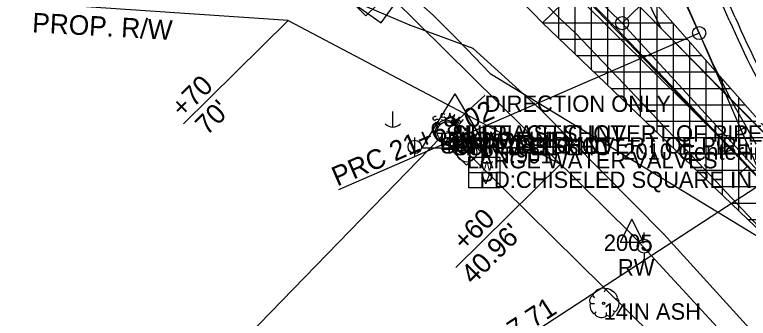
# Model space of a CAD drawing. Extents: x 1660112 to 1662239, y 668919 to 671377.
# Drawn here: x 1661159 to 1661383, y 670095.9 to 670188.6 of the extents above; entities that cross this region are included whole.
import ezdxf

# ---------------------------------------------------------------- set-up
doc = ezdxf.new("R2010")
doc.units = 0
for name, color, linetype in [('R_Annotation', 7, 'Continuous'), ('R_Axis', 7, 'Continuous'), ('R_Horz Alg', 7, 'Continuous'), ('R_Horz Alg Annot', 7, 'Continuous'), ('R_Proposed Const Limits_Cut', 7, 'Continuous'), ('R_Proposed Const Limits_Fill', 7, 'Continuous'), ('R_Proposed Road_Lane', 7, 'Continuous'), ('R_Proposed Road_Shoulder', 7, 'Continuous'), ('R_ROW', 7, 'Continuous'), ('R_ROW Annot', 7, 'Continuous'), ('R_Water Annot', 7, 'Continuous'), ('S_EDGE_CONCRETE', 7, 'Continuous'), ('S_EDGE_PAVEMENT', 7, 'Continuous'), ('S_EXIST_ROW', 7, 'Continuous'), ('S_EXIST_ROW_ANNOT', 7, 'Continuous'), ('S_EXISTING_ALIGNMENT', 7, 'Continuous'), ('S_EXISTING_ALIGNMENT_ANNOT', 7, 'Continuous'), ('S_GRD_PT_SYM', 7, 'Continuous'), ('S_MANHOLE_ANNOT', 7, 'Continuous'), ('S_MISC_TOPO_POINT', 7, 'Continuous'), ('S_PAVEMENT_CROWN', 7, 'Continuous'), ('S_PRIMARY_CTL', 7, 'Continuous'), ('S_PRIMARY_CTL_ANNOT', 7, 'Continuous'), ('S_SANITARY_SEWER', 7, 'Continuous'), ('S_SANITARY_SEWER_ANNOT', 7, 'Continuous'), ('S_TREE', 7, 'Continuous'), ('S_TREE_ANNOT', 7, 'Continuous'), ('S_UTILITY_POLE', 7, 'Continuous'), ('S_UTL_PT_SYM', 7, 'Continuous'), ('S_WATER_UTILITIES', 7, 'Continuous')]:
    doc.layers.add(name, color=color, linetype=linetype)

msp = doc.modelspace()

# ---------------------------------------------------------------- linework, layer by layer
at = {"layer": 'R_Axis'}
for p, q in [((1661340.12, 670166.97), (1661340.12, 670205.5)), ((1661345.12, 670162.18), (1661345.12, 670203.05)), ((1661335.12, 670171.75), (1661335.12, 670200.65)), ((1661350.12, 670157.4), (1661350.12, 670197.37)), ((1661330.12, 670176.53), (1661330.12, 670195.8)), ((1661325.12, 670181.32), (1661325.12, 670190.95)), ((1661355.12, 670152.61), (1661355.12, 670191.69)), ((1661320.12, 670186.1), (1661360.05, 670186.1)), ((1661360.12, 670147.83), (1661360.12, 670186.02)), ((1661325.35, 670181.1), (1661364.45, 670181.1)), ((1661365.12, 670143.05), (1661365.12, 670180.34)), ((1661330.58, 670176.1), (1661368.85, 670176.1)), ((1661370.12, 670138.26), (1661370.12, 670174.66)), ((1661335.8, 670171.1), (1661373.26, 670171.1)), ((1661375.12, 670133.48), (1661375.12, 670168.98)), ((1661341.03, 670166.1), (1661377.66, 670166.1)), ((1661380.12, 670128.7), (1661380.12, 670163.3)), ((1661346.26, 670161.1), (1661382.06, 670161.1)), ((1661351.48, 670156.1), (1661386.46, 670156.1)), ((1661356.71, 670151.1), (1661390.87, 670151.1)), ((1661361.93, 670146.1), (1661395.27, 670146.1)), ((1661367.16, 670141.1), (1661399.67, 670141.1)), ((1661372.39, 670136.1), (1661404.07, 670136.1)), ((1661377.61, 670131.1), (1661407.23, 670131.1)), ((1661382.84, 670126.1), (1661401.94, 670126.1))]:
    msp.add_line(p, q, dxfattribs=at)
msp.add_lwpolyline([(1661320.12, 670186.1), (1661341.66, 670206.99), (1661407.91, 670131.74), (1661392.33, 670117.02)], close=True, dxfattribs=at)
at = {"layer": 'R_Horz Alg'}
for centre, radius, start, end in [((1661098.46, 670065.94), 293.82, 23.4717, 65.7806), ((1655846.99, 664877.91), 7639.44, 42.561815, 45.430038), ((1661637.47, 670300), 293.82, 203.4717, 222.6711), ((1661637.47, 670300), 293.82, 203.4717, 222.6711)]:
    msp.add_arc(centre, radius, start, end, dxfattribs=at)
at = {"layer": 'R_Horz Alg Annot'}
for p, q in [((1661208.2, 670320.2), (1661344.44, 670185.98)), ((1661322.68, 670287.26), (1661367.97, 670182.97)), ((1661344.44, 670185.98), (1661473.81, 670045.11)), ((1661367.97, 670182.97), (1661387.76, 670137.39))]:
    msp.add_line(p, q, dxfattribs=at)
for points in [[(1661344.44, 670185.98), (1661430.77, 670269.33)], [(1661367.97, 670182.97), (1661257.89, 670135.17)], [(1661379.67, 670152.9), (1661382.27, 670154.38)], [(1661380.67, 670140.38), (1661382.84, 670142.45)], [(1661387.76, 670137.39), (1661287.2, 670071.9)]]:
    msp.add_lwpolyline(points, dxfattribs=at)
for centre in [(1661344.44, 670185.98), (1661367.97, 670182.97)]:
    msp.add_circle(centre, 2, dxfattribs=at)
at = {"layer": 'R_Proposed Const Limits_Cut'}
for p, q in [((1661254.1, 670198.04), (1661270.96, 670186.08)), ((1661270.96, 670186.08), (1661278.26, 670196.37))]:
    msp.add_line(p, q, dxfattribs=at)
at = {"layer": 'R_Proposed Const Limits_Fill'}
msp.add_lwpolyline([(1661278.26, 670196.37), (1661284.16, 670190.75), (1661286.76, 670188.4), (1661293.84, 670181.4), (1661297.09, 670178.04), (1661304.19, 670170.65), (1661392.33, 670117.02)], dxfattribs=at)
at = {"layer": 'R_Proposed Road_Lane'}
msp.add_lwpolyline([(1661352.12, 670188.73), (1661394.19, 670145.97), (1661415.33, 670123.89), (1661429.8, 670108.55)], dxfattribs=at)
for centre, radius, start, end in [((1661098.46, 670065.94), 303.82, 23.4717, 65.7806), ((1661098.46, 670065.94), 283.82, 24.6629, 65.2815), ((1661637.47, 670300), 283.82, 203.4717, 217.6784)]:
    msp.add_arc(centre, radius, start, end, dxfattribs=at)
at = {"layer": 'R_Proposed Road_Shoulder'}
msp.add_line((1661320.12, 670186.1), (1661323, 670188.89), dxfattribs=at)
for centre, radius, start, end in [((1661098.46, 670065.94), 305.82, 23.4717, 65.7806), ((1655846.99, 664877.91), 7624.44, 44.123518, 45.136018), ((1661637.47, 670300), 281.82, 203.4717, 217.6583)]:
    msp.add_arc(centre, radius, start, end, dxfattribs=at)
at = {"layer": 'R_ROW'}
for q in [(1661144.3, 670193.47), (1661325.67, 670142.98)]:
    msp.add_line((1661242.56, 670186.79), q, dxfattribs=at)
at = {"layer": 'R_ROW Annot'}
for p, q in [((1661242.56, 670186.79), (1661210.56, 670155.28)), ((1661325.67, 670142.98), (1661293.66, 670111.47))]:
    msp.add_line(p, q, dxfattribs=at)
at = {"layer": 'R_Water Annot'}
msp.add_lwpolyline([(1661208.1, 670261.48), (1661201.05, 670254.4), (1661266.25, 670188.25), (1661273.39, 670195.25), (1661272.84, 670195.64), (1661283.61, 670210.8), (1661236.51, 670258.15), (1661208.04, 670260.82)], close=True, dxfattribs=at)
at = {"layer": 'S_EDGE_CONCRETE'}
msp.add_lwpolyline([(1661293, 670149.81), (1661293.5, 670150.75), (1661294.22, 670151.81), (1661294.22, 670153.16), (1661293.96, 670154.35), (1661293.3, 670155.31), (1661292.45, 670155.96), (1661291.31, 670156.34), (1661290.11, 670156.43), (1661288.99, 670155.89), (1661287.99, 670154.78), (1661287.69, 670153.93), (1661287.29, 670153.06), (1661287.65, 670151.62), (1661287.94, 670150.85), (1661288.74, 670150.02), (1661289.46, 670149.65), (1661290.67, 670149.36), (1661291.56, 670149.44), (1661293.01, 670149.87)], dxfattribs=at)
msp.add_lwpolyline([(1661292.81, 670146.81), (1661297, 670142.7), (1661301.21, 670146.85), (1661297.06, 670151.06)], close=True, dxfattribs=at)
at = {"layer": 'S_EDGE_PAVEMENT'}
for points in [[(1661528.89, 670006.64), (1661525.81, 670010.93), (1661521.19, 670007.06), (1661512.12, 670017.42), (1661503.06, 670027.78), (1661494.14, 670038.45), (1661485.22, 670049.12), (1661475.65, 670058.13), (1661469.7, 670064.69), (1661453.26, 670082.63), (1661441.58, 670095.54), (1661429.9, 670108.45), (1661415.33, 670123.89), (1661400.76, 670139.32), (1661387.62, 670152.61), (1661374.47, 670165.9), (1661358.81, 670181.9), (1661343.14, 670197.9), (1661339.48, 670201.44), (1661329.75, 670211.05), (1661320.02, 670220.65), (1661304.77, 670236.19)], [(1661507.57, 669985.17), (1661503.63, 669990.55), (1661503.83, 669996.41), (1661492.59, 670008.33), (1661484.98, 670015.56), (1661475.91, 670025.37), (1661466.84, 670035.18), (1661454.4, 670049.73), (1661445.95, 670059), (1661437.51, 670068.28), (1661425.39, 670081.13), (1661413.28, 670093.99), (1661399.68, 670108.94), (1661386.08, 670123.89), (1661373.13, 670137.66), (1661360.18, 670151.43), (1661345.14, 670167.24), (1661330.11, 670183.04), (1661325.69, 670187.24), (1661316.74, 670196.41), (1661307.8, 670205.57), (1661291.28, 670222.16)]]:
    msp.add_lwpolyline(points, dxfattribs=at)
at = {"layer": 'S_EXIST_ROW'}
for p, q in [((1661347.41, 670121.48), (1660345.19, 671112.79)), ((1661347.42, 670126.21), (1661343.89, 670119.12)), ((1661347.42, 670126.21), (1661350.91, 670119.12)), ((1661347.41, 670121.48), (1661347.41, 670121.48)), ((1661563.48, 669887.93), (1661347.41, 670121.48)), ((1661343.89, 670119.12), (1661350.91, 670119.12))]:
    msp.add_line(p, q, dxfattribs=at)
for radius in [0.12, 0.06]:
    msp.add_circle((1661347.41, 670121.48), radius, dxfattribs=at)
at = {"layer": 'S_EXISTING_ALIGNMENT'}
for p, q in [((1661376.17, 670149.3), (1660373.32, 671141.23)), ((1661613.41, 669892.86), (1661376.17, 670149.3))]:
    msp.add_line(p, q, dxfattribs=at)
msp.add_circle((1661376.17, 670149.3), 2.5, dxfattribs=at)
at = {"layer": 'S_GRD_PT_SYM'}
for points in [[(1661292.56, 670154.83), (1661292.56, 670154.88), (1661292.56, 670154.83), (1661292.51, 670154.83), (1661292.56, 670154.83), (1661292.56, 670154.78), (1661292.56, 670154.83), (1661292.61, 670154.83)], [(1661289.08, 670151.19), (1661289.08, 670151.24), (1661289.08, 670151.19), (1661289.03, 670151.19), (1661289.08, 670151.19), (1661289.08, 670151.14), (1661289.08, 670151.19), (1661289.13, 670151.19)], [(1661292.91, 670150.69), (1661292.91, 670150.74), (1661292.91, 670150.69), (1661292.86, 670150.69), (1661292.91, 670150.69), (1661292.91, 670150.64), (1661292.91, 670150.69), (1661292.96, 670150.69)]]:
    msp.add_lwpolyline(points, dxfattribs=at)
at = {"layer": 'S_PAVEMENT_CROWN'}
msp.add_lwpolyline([(1661518.06, 669996.03), (1661505.4, 670009.31), (1661492.74, 670022.59), (1661480.19, 670036.99), (1661467.64, 670051.39), (1661473.76, 670044.39), (1661461.34, 670057.98), (1661445.4, 670075.38), (1661443.99, 670076.39), (1661432.69, 670088.65), (1661421.39, 670100.9), (1661407.48, 670115.88), (1661393.57, 670130.85), (1661380.41, 670144.59), (1661367.25, 670158.33), (1661351.88, 670174.26), (1661336.51, 670190.18), (1661332.38, 670194.36), (1661323.21, 670203.51), (1661314.05, 670212.66), (1661297.56, 670228.68)], dxfattribs=at)
at = {"layer": 'S_PRIMARY_CTL'}
for p, q in [((1661293.39, 670164.41), (1661283.35, 670147.9)), ((1661293.39, 670164.41), (1661303.21, 670147.9)), ((1661283.35, 670147.9), (1661303.21, 670147.9))]:
    msp.add_line(p, q, dxfattribs=at)
for radius in [1.04, 0.609, 0.344]:
    msp.add_circle((1661293.39, 670155.71), radius, dxfattribs=at)
at = {"layer": 'S_SANITARY_SEWER'}
for p, q in [((1661292.56, 670154.83), (1661302.51, 670163.92)), ((1661286.73, 670157.16), (1661286.65, 670156.77)), ((1661286.65, 670156.77), (1661286.84, 670156.5)), ((1661287.27, 670157.55), (1661286.73, 670157.16)), ((1661286.84, 670156.5), (1661287.27, 670156.38)), ((1661287.69, 670157.47), (1661287.27, 670157.55)), ((1661287.27, 670156.38), (1661287.81, 670156.73)), ((1661287.81, 670156.73), (1661288.28, 670156.65)), ((1661288.28, 670156.65), (1661288.43, 670156.38)), ((1661288.43, 670156.38), (1661288.35, 670155.96)), ((1661293.7, 670155.92), (1661294.94, 670157.39)), ((1661294.36, 670156.69), (1661295.33, 670155.88)), ((1661295.91, 670156.58), (1661294.67, 670155.1)), ((1661287.81, 670155.57), (1661287.42, 670155.65)), ((1661288.35, 670155.96), (1661287.81, 670155.57)), ((1661289.08, 670151.19), (1660996.93, 669850.58)), ((1661292.72, 670150.97), (1661292.64, 670150.59)), ((1661292.64, 670150.59), (1661292.83, 670150.31)), ((1661293.26, 670151.36), (1661292.72, 670150.97)), ((1661292.83, 670150.31), (1661293.26, 670150.2)), ((1661704.02, 669745.54), (1661292.91, 670150.69)), ((1661293.69, 670151.28), (1661293.26, 670151.36)), ((1661293.26, 670150.2), (1661293.8, 670150.55)), ((1661293.8, 670150.55), (1661294.27, 670150.47)), ((1661294.34, 670149.77), (1661293.8, 670149.38)), ((1661294.27, 670150.47), (1661294.42, 670150.2)), ((1661294.42, 670150.2), (1661294.34, 670149.77)), ((1661299.69, 670149.73), (1661300.93, 670151.21)), ((1661300.35, 670150.51), (1661301.32, 670149.69)), ((1661301.9, 670150.39), (1661300.66, 670148.92)), ((1661293.8, 670149.38), (1661293.41, 670149.46))]:
    msp.add_line(p, q, dxfattribs=at)
for points in [[(1661292.81, 670156.23), (1661293.35, 670158.09), (1661292.31, 670157.08), (1661291.92, 670158.51), (1661291.38, 670156.65)], [(1661290.37, 670158.09), (1661290.02, 670158.36), (1661289.36, 670158.28), (1661289.13, 670157.93), (1661289.17, 670157.62), (1661289.52, 670157.31), (1661290.14, 670157.43), (1661290.52, 670157.12), (1661290.56, 670156.81), (1661290.29, 670156.42), (1661289.67, 670156.34), (1661289.32, 670156.62)], [(1661296.36, 670151.9), (1661296.01, 670152.17), (1661295.35, 670152.1), (1661295.12, 670151.75), (1661295.16, 670151.44), (1661295.51, 670151.13), (1661296.13, 670151.24), (1661296.51, 670150.93), (1661296.55, 670150.62), (1661296.28, 670150.24), (1661295.66, 670150.16), (1661295.31, 670150.43)], [(1661298.8, 670150.04), (1661299.34, 670151.9), (1661298.3, 670150.9), (1661297.91, 670152.33), (1661297.37, 670150.47)]]:
    msp.add_lwpolyline(points, dxfattribs=at)
for centre in [(1661291.05, 670152.85), (1661297.04, 670146.67)]:
    msp.add_circle(centre, 3.05, dxfattribs=at)
at = {"layer": 'S_TREE'}
for p, q in [((1661339.36, 670104.75), (1661338.97, 670103.9)), ((1661335.56, 670102.74), (1661336.06, 670102.16)), ((1661334.9, 670100.41), (1661336.02, 670100.41)), ((1661342.92, 670101.96), (1661342.26, 670101.69)), ((1661342.15, 670097.86), (1661341.68, 670098.28)), ((1661336.06, 670097.24), (1661336.53, 670097.93)), ((1661339.74, 670096.97), (1661339.67, 670097.74))]:
    msp.add_line(p, q, dxfattribs=at)
msp.add_circle((1661338.8, 670100.51), 0.341, dxfattribs=at)
for centre, major_axis, ratio, start_param, end_param in [((1661337.46, 670103.71), (1.86, 1.08), 0.471018, 0, 3.141593), ((1661341.12, 670103.39), (-1.81, 1.36), 0.405113, 3.141593, 6.283186), ((1661335.23, 670101.6), (0.31, 1.03), 0.646762, 0, 3.141593), ((1661335.53, 670098.95), (-0.61, 1.6), 0.420543, 6.283185, 9.424777), ((1661342.47, 670099.98), (0.46, 2.04), 0.482994, 3.141593, 6.283185), ((1661337.99, 670097.17), (-1.83, 0.19), 0.529943, 0, 3.141593), ((1661340.95, 670097.46), (1.09, 0.46), 0.711534, 3.141592, 6.283185)]:
    msp.add_ellipse(centre, major_axis=major_axis, ratio=ratio, start_param=start_param, end_param=end_param, dxfattribs=at)
at = {"layer": 'S_UTILITY_POLE'}
for p, q in [((1661274.4, 670159.02), (1661274.4, 670154.29)), ((1661281.16, 670145.3), (1661281.16, 670151.09)), ((1661351.17, 670120.02), (1661351.17, 670122.15)), ((1661351.17, 670115.8), (1661351.17, 670113.74))]:
    msp.add_line(p, q, dxfattribs=at)
for centre, radius in [((1661281.16, 670148.23), 2.05), ((1661351.19, 670117.94), 2.11)]:
    msp.add_circle(centre, radius, dxfattribs=at)
msp.add_arc((1661274.46, 670157.71), 3.41, 226.3972, 313.6028, dxfattribs=at)
at = {"layer": 'S_UTL_PT_SYM'}
for points in [[(1661279.71, 670185.37), (1661279.71, 670185.42), (1661279.71, 670185.37), (1661279.66, 670185.37), (1661279.71, 670185.37), (1661279.71, 670185.32), (1661279.71, 670185.37), (1661279.76, 670185.37)], [(1661298.96, 670178.23), (1661298.96, 670178.28), (1661298.96, 670178.23), (1661298.91, 670178.23), (1661298.96, 670178.23), (1661298.96, 670178.18), (1661298.96, 670178.23), (1661299.01, 670178.23)], [(1661302.51, 670163.92), (1661302.51, 670163.97), (1661302.51, 670163.92), (1661302.45, 670163.92), (1661302.51, 670163.92), (1661302.51, 670163.87), (1661302.51, 670163.92), (1661302.55, 670163.92)], [(1661319.59, 670159.62), (1661319.59, 670159.67), (1661319.59, 670159.62), (1661319.54, 670159.62), (1661319.59, 670159.62), (1661319.59, 670159.57), (1661319.59, 670159.62), (1661319.64, 670159.62)], [(1661292.56, 670154.83), (1661292.56, 670154.88), (1661292.56, 670154.83), (1661292.51, 670154.83), (1661292.56, 670154.83), (1661292.56, 670154.78), (1661292.56, 670154.83), (1661292.61, 670154.83)], [(1661291.05, 670152.85), (1661291.05, 670152.9), (1661291.05, 670152.85), (1661291, 670152.85), (1661291.05, 670152.85), (1661291.05, 670152.8), (1661291.05, 670152.85), (1661291.1, 670152.85)], [(1661289.08, 670151.19), (1661289.08, 670151.24), (1661289.08, 670151.19), (1661289.03, 670151.19), (1661289.08, 670151.19), (1661289.08, 670151.14), (1661289.08, 670151.19), (1661289.13, 670151.19)], [(1661292.91, 670150.69), (1661292.91, 670150.74), (1661292.91, 670150.69), (1661292.86, 670150.69), (1661292.91, 670150.69), (1661292.91, 670150.64), (1661292.91, 670150.69), (1661292.96, 670150.69)], [(1661357.16, 670121.64), (1661357.16, 670121.69), (1661357.16, 670121.64), (1661357.11, 670121.64), (1661357.16, 670121.64), (1661357.16, 670121.58), (1661357.16, 670121.64), (1661357.21, 670121.64)]]:
    msp.add_lwpolyline(points, dxfattribs=at)
at = {"layer": 'S_WATER_UTILITIES'}
for p, q in [((1661279.71, 670185.37), (1661262.17, 670192.84)), ((1661298.96, 670178.23), (1661279.71, 670185.37)), ((1661319.59, 670159.62), (1661298.96, 670178.23)), ((1661357.16, 670121.64), (1661319.59, 670159.62)), ((1661297.71, 670145.12), (1661307.13, 670145.12)), ((1661297.71, 670135.7), (1661297.71, 670145.12)), ((1661307.13, 670145.12), (1661307.13, 670135.7)), ((1661297.71, 670140.43), (1661307.13, 670140.43)), ((1661307.13, 670135.7), (1661297.71, 670135.7)), ((1661406.96, 670066.82), (1661357.16, 670121.64))]:
    msp.add_line(p, q, dxfattribs=at)

# ---------------------------------------------------------------- texts
at = {"layer": 'R_Annotation'}
msp.add_text('PROP. R/W', height=6, rotation=356.8913, dxfattribs=at).set_placement((1661164.29, 670183.2))
at = {"layer": 'R_Horz Alg Annot'}
for s, rotation, p in [('PRC 21+68.02', 23.4717, (1661257.5, 670136.09)), ('PI  22+17.71', 33.0714, (1661286.65, 670072.74))]:
    msp.add_text(s, height=6, rotation=rotation, dxfattribs=at).set_placement(p)
at = {"layer": 'R_ROW Annot'}
for s, p in [('+70', (1661210.35, 670156.81)), ("70'", (1661217.75, 670151.47)), ('+60', (1661296.39, 670116.14)), ("40.96'", (1661298.93, 670105.97))]:
    msp.add_text(s, height=6, rotation=44.7873, dxfattribs=at).set_placement(p)
at = {"layer": 'S_EXIST_ROW_ANNOT'}
for s, p in [('2005', (1661338.86, 670116.48)), ('RW', (1661343.19, 670108.98))]:
    msp.add_text(s, height=5, dxfattribs=at).set_placement(p)
at = {"layer": 'S_EXISTING_ALIGNMENT_ANNOT'}
msp.add_text('2010 Centerline', height=5, dxfattribs=at).set_placement((1661344.83, 670144.3))
at = {"layer": 'S_MANHOLE_ANNOT'}
for s, p in [('FLOW LINE', (1661291.05, 670147.85)), ('LARGE WATER VALVES', (1661297.04, 670141.67))]:
    msp.add_text(s, height=5, dxfattribs=at).set_placement(p)
at = {"layer": 'S_MISC_TOPO_POINT'}
for p in [(1661292.56, 670149.83), (1661289.08, 670146.19), (1661292.91, 670145.69)]:
    msp.add_text('SURFACE SHOT', height=5, dxfattribs=at).set_placement(p)
at = {"layer": 'S_PRIMARY_CTL'}
msp.add_text('TBM', height=4.287, rotation=360, dxfattribs=at).set_placement((1661287.74, 670148.32))
at = {"layer": 'S_PRIMARY_CTL_ANNOT'}
for s, p in [('PN:901', (1661300.89, 670143.21)), ('PD:CHISELED SQUARE IN CONC', (1661300.89, 670135.71))]:
    msp.add_text(s, height=5, dxfattribs=at).set_placement(p)
at = {"layer": 'S_SANITARY_SEWER_ANNOT'}
for s, p in [('DIRECTION ONLY', (1661302.51, 670158.92)), ('4IN PLASTIC INVERT OF PIPE', (1661292.56, 670149.83)), ('TOP OF LID', (1661291.05, 670147.85)), ('4IN PLASTIC INVERT OF PIPE', (1661289.08, 670146.19)), ('4IN PLASTIC', (1661292.91, 670145.69))]:
    msp.add_text(s, height=5, dxfattribs=at).set_placement(p)
at = {"layer": 'S_TREE_ANNOT'}
msp.add_text('14IN ASH', height=5, dxfattribs=at).set_placement((1661338.8, 670095.51))
at = {"layer": 'S_WATER_UTILITIES'}
for s, p in [('W', (1661301.26, 670140.96)), ('V', (1661301.5, 670136.9))]:
    msp.add_text(s, height=3, rotation=360, dxfattribs=at).set_placement(p)

doc.saveas('drawing.dxf')
